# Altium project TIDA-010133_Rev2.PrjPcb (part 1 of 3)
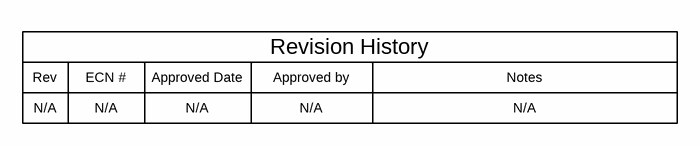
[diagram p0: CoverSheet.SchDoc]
CCA REV: A; CopyrightYear: 2023; ESD REV: A; EVM_orderable: N/A; PCB_Layout: TESSOLVE; PCB_Rev: B; PRJ_Customer: Public Release; PRJ_Engineer: Rob Stoneham; PRJ_Number: TIDA-010133; PRJ_Title: TIDA-010133; SCH_Rev: B; TechSupport: http://www.ti.com/support; TID: N/A
8 sheets, 588 parts. Net scope: flat (ports and power ports of the same name join across sheets).
Board file: TIDA010133_PCB.PcbDoc
Sheets:
  CoverSheet.SchDoc
  1_BUF802_CH1_AFE.SchDoc
  2_BUF802_CH2_AFE.SchDoc
  3_BUF802_OFFSET_TRIGGER.SchDoc
  4_BUF802_USBIF.SchDoc
  5_BUF802_PWR_PG1.SchDoc
  6_BUF802_PWR_PG2.SchDoc
  EVM_Hardware.SchDoc

## Sheet CoverSheet.SchDoc: CoverSheet
size 431 x 279 mm; Date: Not shown in title block; ApprovedBy: Not shown in title block; CheckedBy: Not shown in title block; Author: Not shown in title block; CompanyName: Not shown in title block; DrawnBy: Rob Stoneham; Engineer: Not shown in title block; Organization: Not shown in title block; Address1: Not shown in title block; Address2: Not shown in title block; Address3: Not shown in title block; Address4: Not shown in title block; DocumentNumber: 1; Revision: Use project parameter SCH_Rev; SheetNumber: 1; SheetTotal: 8; PageSetup: Record=PageOptions¦CenterHorizontal=True¦CenterVertical=True¦PrintScale=1.00¦XCorrection=1.00¦YCorrection=1.00¦PrintKind=0¦BorderSize=5000000¦LeftOffset=0¦BottomOffset=0¦Orientation=2¦PaperLength=1000¦PaperWidth=1000¦Scale=100¦PaperSource=15¦PrintQuality=600¦MediaType=1¦DitherType=10¦PaperKind=Letter¦PrintScaleMode=1

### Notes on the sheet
- Rev
- N/A
- ECN #
- Approved Date
- Approved by
- Revision History
- Notes

## Sheet 1_BUF802_CH1_AFE.SchDoc: 1_BUF802_CH1_AFE
size 431 x 279 mm; Date: Not shown in title block; ApprovedBy: Not shown in title block; CheckedBy: Not shown in title block; Author: Not shown in title block; CompanyName: Not shown in title block; DrawnBy: Rob Stoneham; Engineer: Not shown in title block; Organization: Not shown in title block; Address1: Not shown in title block; Address2: Not shown in title block; Address3: Not shown in title block; Address4: Not shown in title block; DocumentNumber: 2; Revision: Use project parameter SCH_Rev; SheetNumber: 2; SheetTotal: 8; PageSetup: Record=PageOptions¦CenterHorizontal=True¦CenterVertical=True¦PrintScale=1.00¦XCorrection=1.00¦YCorrection=1.00¦PrintKind=0¦BorderSize=5000000¦LeftOffset=0¦BottomOffset=0¦Orientation=2¦PaperLength=1000¦PaperWidth=1000¦Scale=100¦PaperSource=15¦PrintQuality=600¦MediaType=1¦DitherType=10¦PaperKind=Letter¦PrintScaleMode=1
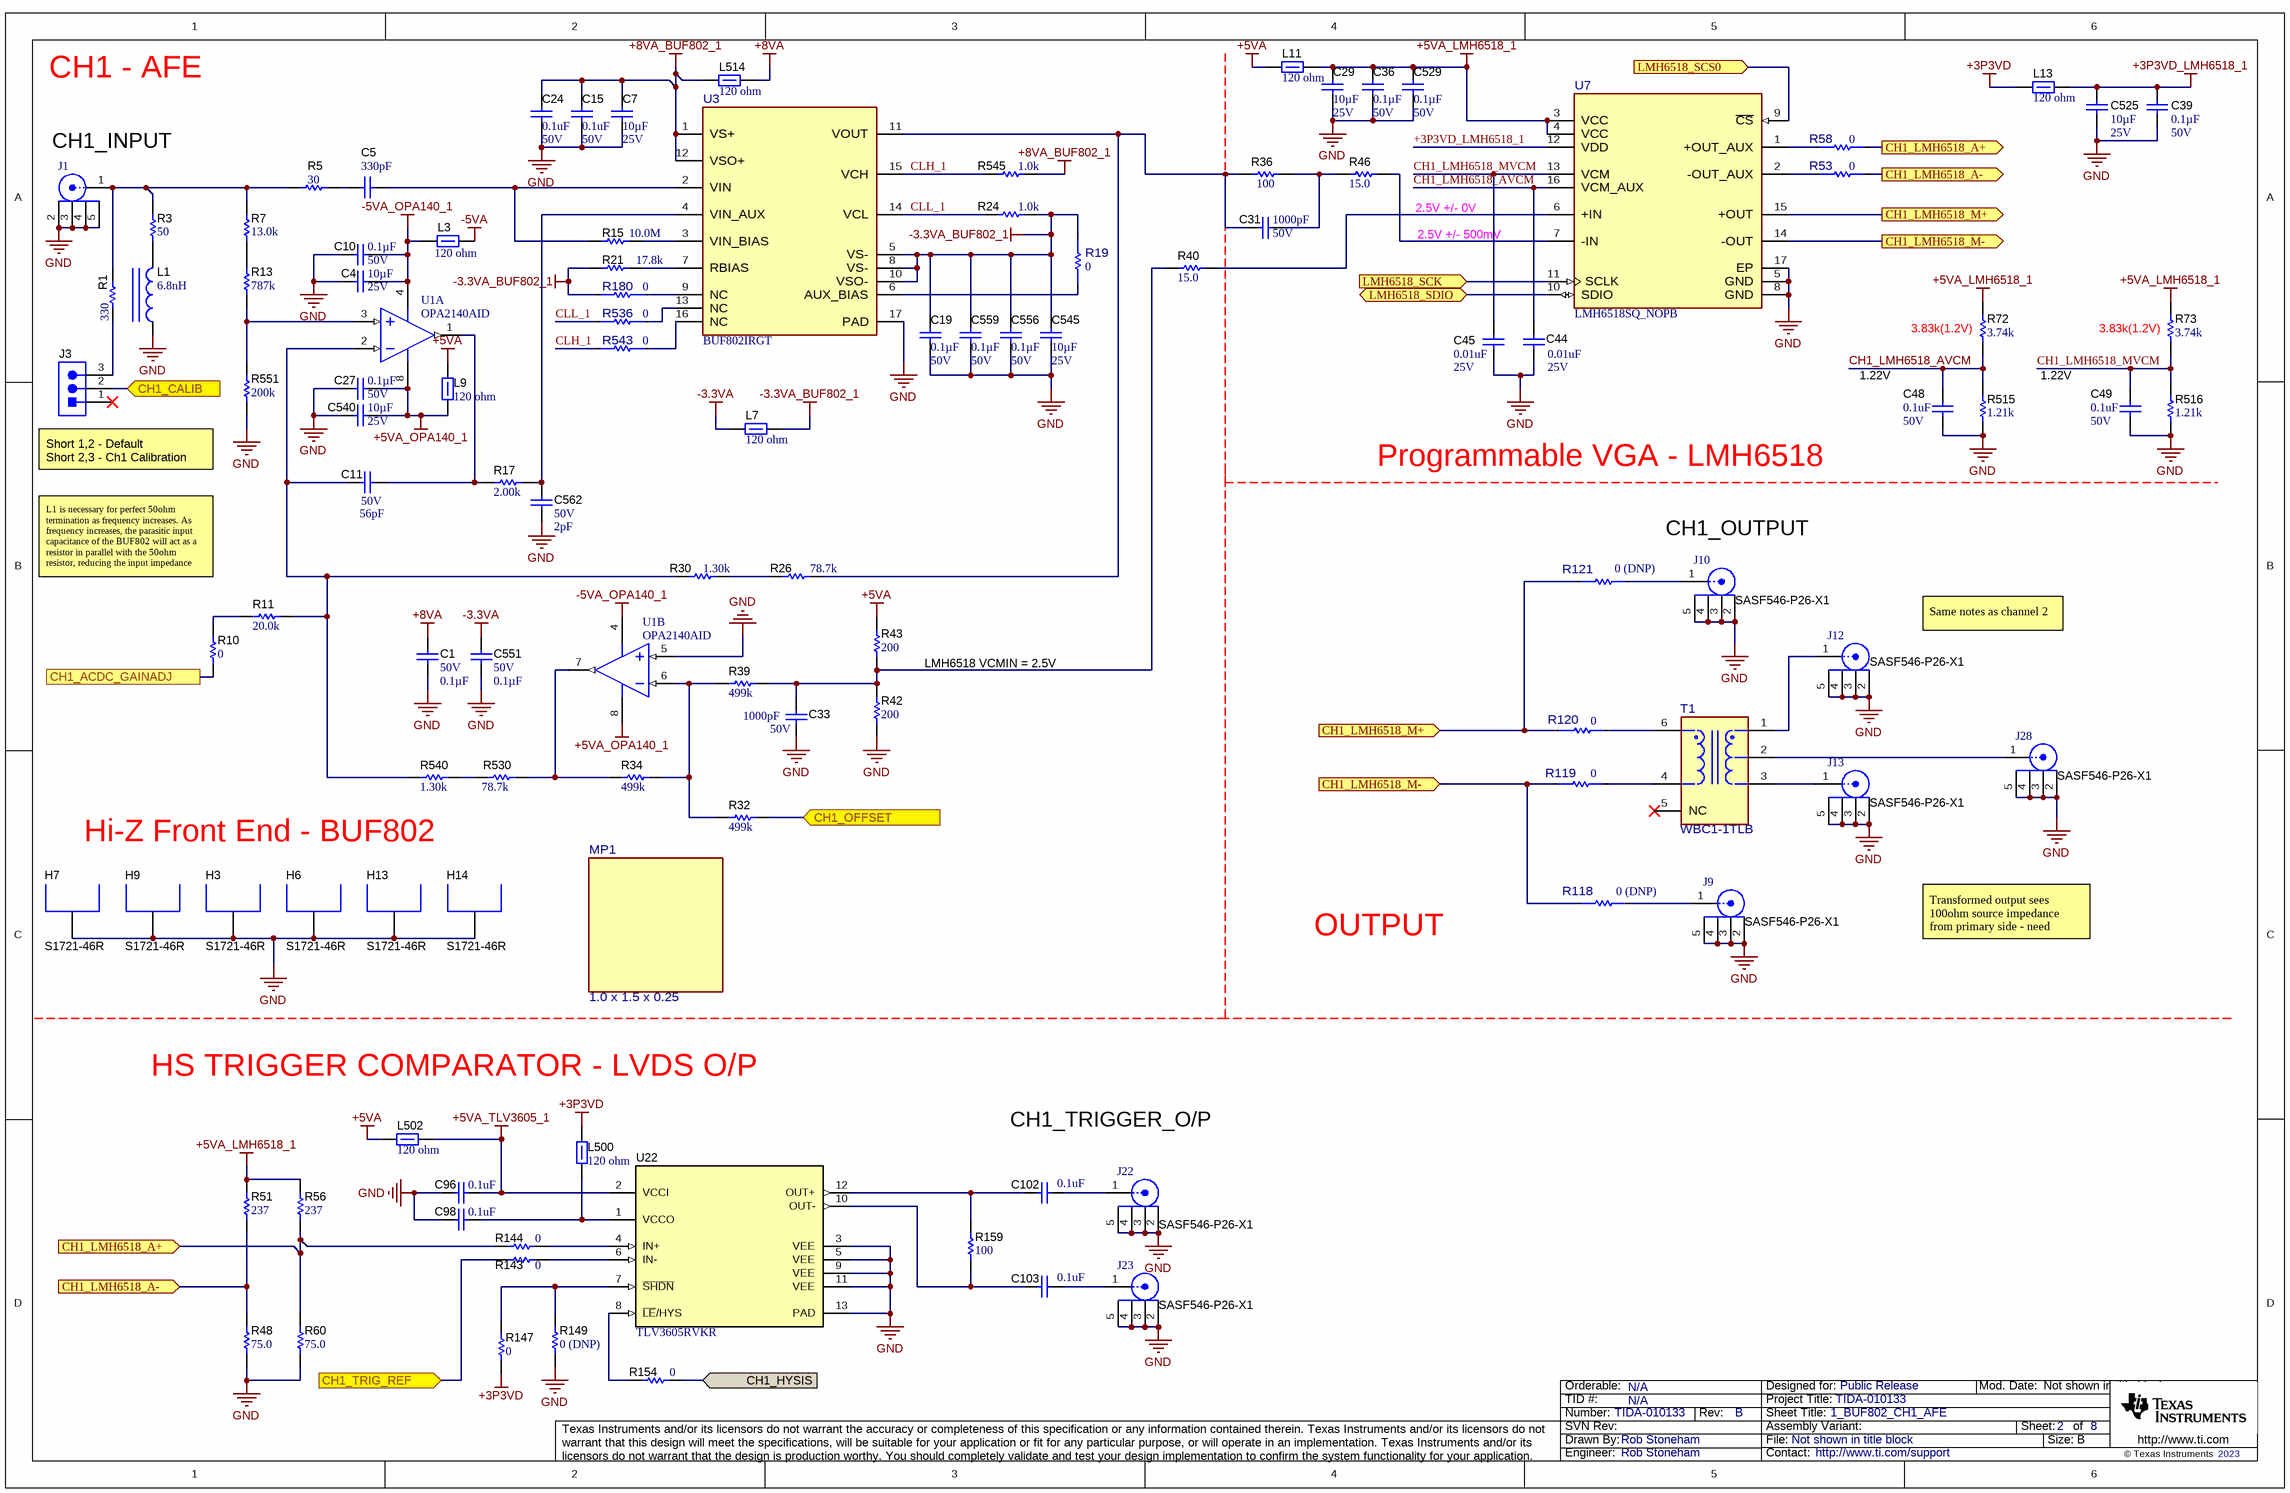
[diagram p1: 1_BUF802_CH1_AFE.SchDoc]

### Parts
C1  VDC_V: 50V  ValueDisplayed: 0.1µF  [0402]  (hidden comment: 0402BB104KW500)
C4  VDC_V: 25V  ValueDisplayed: 10µF  [0805_HV]  (hidden comment: CC0805KKX5R8BB106)
C5  ValueDisplayed: 330pF  [1206]  (hidden comment: GRM31A5C2J331JW01D)
C7  VDC_V: 25V  ValueDisplayed: 10µF  [0805_HV]  (hidden comment: CC0805KKX5R8BB106)
C10  VDC_V: 50V  ValueDisplayed: 0.1µF  [0402]  (hidden comment: 0402BB104KW500)
C11  VDC_V: 50V  ValueDisplayed: 56pF  [0402]  (hidden comment: GRM1555C1H560JA01D)
C15  ValueDisplayed: 0.1uF  Value2: 50V  [0603]  (hidden comment: CGA3E2X7R1H104K080AA)
C19  VDC_V: 50V  ValueDisplayed: 0.1µF  [0402]  (hidden comment: 0402BB104KW500)
C24  ValueDisplayed: 0.1uF  Value2: 50V  [0603]  (hidden comment: CGA3E2X7R1H104K080AA)
C27  VDC_V: 50V  ValueDisplayed: 0.1µF  [0402]  (hidden comment: 0402BB104KW500)
C29  VDC_V: 25V  ValueDisplayed: 10µF  [0805_HV]  (hidden comment: CC0805KKX5R8BB106)
C31  VDC_V: 50V  ValueDisplayed: 1000pF  [0402]  (hidden comment: 885012205061)
C33  VDC_V: 50V  ValueDisplayed: 1000pF  [0402]  (hidden comment: 885012205061)
C36  VDC_V: 50V  ValueDisplayed: 0.1µF  [0402]  (hidden comment: 0402BB104KW500)
C39  VDC_V: 50V  ValueDisplayed: 0.1µF  [0402]  (hidden comment: 0402BB104KW500)
C44  ValueDisplayed: 0.01uF  VDC_V: 25V  [0306]  (hidden comment: LLL185R71E103MA01L)
C45  ValueDisplayed: 0.01uF  VDC_V: 25V  [0306]  (hidden comment: LLL185R71E103MA01L)
C48  ValueDisplayed: 0.1uF  VDC_V: 50V  [0603]  (hidden comment: CGA3E2X7R1H104K080AA)
C49  ValueDisplayed: 0.1uF  VDC_V: 50V  [0603]  (hidden comment: CGA3E2X7R1H104K080AA)
C96  ValueDisplayed: 0.1uF  [0603]  (hidden comment: CGA3E2X7R1H104K080AA)
C98  ValueDisplayed: 0.1uF  [0603]  (hidden comment: CGA3E2X7R1H104K080AA)
C102  ValueDisplayed: 0.1uF  [0402]  (hidden comment: C1005X7R1E104M050BB)
C103  ValueDisplayed: 0.1uF  [0402]  (hidden comment: C1005X7R1E104M050BB)
C525  VDC_V: 25V  ValueDisplayed: 10µF  [0805_HV]  (hidden comment: CC0805KKX5R8BB106)
C529  VDC_V: 50V  ValueDisplayed: 0.1µF  [0402]  (hidden comment: 0402BB104KW500)
C540  VDC_V: 25V  ValueDisplayed: 10µF  [0805_HV]  (hidden comment: CC0805KKX5R8BB106)
C545  VDC_V: 25V  ValueDisplayed: 10µF  [0805_HV]  (hidden comment: CC0805KKX5R8BB106)
C551  VDC_V: 50V  ValueDisplayed: 0.1µF  [0402]  (hidden comment: 0402BB104KW500)
C556  VDC_V: 50V  ValueDisplayed: 0.1µF  [0402]  (hidden comment: 0402BB104KW500)
C559  VDC_V: 50V  ValueDisplayed: 0.1µF  [0402]  (hidden comment: 0402BB104KW500)
C562  VDC_V: 50V  ValueDisplayed: 2pF  [0603]  (hidden comment: C0603C209C5GACTU)
H3  S1721-46R  [Harwin_S1721-46R]
H6  S1721-46R  [Harwin_S1721-46R]
H7  S1721-46R  [Harwin_S1721-46R]
H9  S1721-46R  [Harwin_S1721-46R]
H13  S1721-46R  [Harwin_S1721-46R]
H14  S1721-46R  [Harwin_S1721-46R]
J1  142-0701-851  [Emerson_142-0701-851]  (value not drawn)
J3  22284030  [Molex_0022284030]  (value not drawn)
J9  SASF546-P26-X1  [CONN_LTI_SASF546-P26-X1]
J10  SASF546-P26-X1  [CONN_LTI_SASF546-P26-X1]
J12  SASF546-P26-X1  [CONN_LTI_SASF546-P26-X1]
J13  SASF546-P26-X1  [CONN_LTI_SASF546-P26-X1]
J22  SASF546-P26-X1  [CONN_LTI_SASF546-P26-X1]
J23  SASF546-P26-X1  [CONN_LTI_SASF546-P26-X1]
J28  SASF546-P26-X1  [CONN_LTI_SASF546-P26-X1]
L1  ValueDisplayed: 6.8nH  [LQG15WZ_02]  (hidden comment: LQG15WZ6N8J02D)
L3  ValueDisplayed: 120 ohm  [0603]  (hidden comment: BLM18SG121TN1D)
L7  ValueDisplayed: 120 ohm  [0603]  (hidden comment: BLM18SG121TN1D)
L9  ValueDisplayed: 120 ohm  [0603]  (hidden comment: BLM18SG121TN1D)
L11  ValueDisplayed: 120 ohm  [0603]  (hidden comment: BLM18SG121TN1D)
L13  ValueDisplayed: 120 ohm  [0603]  (hidden comment: BLM18SG121TN1D)
L500  ValueDisplayed: 120 ohm  [0603]  (hidden comment: BLM18SG121TN1D)
L502  ValueDisplayed: 120 ohm  [0603]  (hidden comment: BLM18SG121TN1D)
L514  ValueDisplayed: 120 ohm  [0603]  (hidden comment: BLM18SG121TN1D)
MP1  1.0 x 1.5 x 0.25  [FP-1.0 x 1.5 x 0.25_RF_SHIELD-MFG]
R1  ValueDisplayed: 330  [0603]  (hidden comment: RC0603FR-07330RL)
R3  ValueDisplayed: 50  [0603]  (hidden comment: FC0603E50R0BTBST1)
R5  ValueDisplayed: 30  [0402]  (hidden comment: CRCW040230R0JNED)
R7  ValueDisplayed: 13.0k  [0402L]  (hidden comment: CRCW040213K0FKED)
R10  ValueDisplayed: 0  [0603]  (hidden comment: CRCW06030000Z0EA)
R11  ValueDisplayed: 20.0k  [0402]  (hidden comment: CRCW040220K0FKED)
R13  ValueDisplayed: 787k  [0402L]  (hidden comment: CRCW0402787KFKED)
R15  ValueDisplayed: 10.0M  [0402]  (hidden comment: CRCW040210M0FKED)
R17  ValueDisplayed: 2.00k  [0402]  (hidden comment: ERJ-2RKF2001X)
R19  value 0  [FP-ERJ-2GE0R00X_0402-MFG]  (hidden comment: ERJ-2GE0R00X)
R21  ValueDisplayed: 17.8k  [0402]  (hidden comment: CRCW040217K8FKED)
R24  ValueDisplayed: 1.0k  [0603]  (hidden comment: RC0603JR-071KL)
R26  ValueDisplayed: 78.7k  [0402]  (hidden comment: CRCW040278K7FKED)
R30  ValueDisplayed: 1.30k  [0402]  (hidden comment: CRCW04021K30FKED)
R32  ValueDisplayed: 499k  [0402]  (hidden comment: CRCW0402499KFKED)
R34  ValueDisplayed: 499k  [0402]  (hidden comment: CRCW0402499KFKED)
R36  ValueDisplayed: 100  [0402]  (hidden comment: CRCW0402100RFKED)
R39  ValueDisplayed: 499k  [0402]  (hidden comment: CRCW0402499KFKED)
R40  ValueDisplayed: 15.0  [0402]  (hidden comment: CRCW040215R0FKED)
R42  ValueDisplayed: 200  [0402]  (hidden comment: CRCW0402200RFKED)
R43  ValueDisplayed: 200  [0402]  (hidden comment: CRCW0402200RFKED)
R46  ValueDisplayed: 15.0  [0402]  (hidden comment: CRCW040215R0FKED)
R48  ValueDisplayed: 75.0  [0603]  (hidden comment: CRCW060375R0FKEA)
R51  ValueDisplayed: 237  [0603]  (hidden comment: CRCW0603237RFKEA)
R53  value 0  [FP-CRCW04020000Z0EDHP_0402-MFG]  (hidden comment: CRCW04020000Z0EDHP)
R56  ValueDisplayed: 237  [0603]  (hidden comment: CRCW0603237RFKEA)
R58  value 0  [FP-CRCW04020000Z0EDHP_0402-MFG]  (hidden comment: CRCW04020000Z0EDHP)
R60  ValueDisplayed: 75.0  [0603]  (hidden comment: CRCW060375R0FKEA)
R72  ValueDisplayed: 3.74k  [0603]  (hidden comment: RC0603FR-073K74L)
R73  ValueDisplayed: 3.74k  [0603]  (hidden comment: RC0603FR-073K74L)
R118  value 0 (DNP)  [FP-CRCW04020000Z0EDHP_0402-MFG]  (hidden comment: CRCW04020000Z0EDHP)
R119  value 0  [FP-CRCW04020000Z0EDHP_0402-MFG]  (hidden comment: CRCW04020000Z0EDHP)
R120  value 0  [FP-CRCW04020000Z0EDHP_0402-MFG]  (hidden comment: CRCW04020000Z0EDHP)
R121  value 0 (DNP)  [FP-CRCW04020000Z0EDHP_0402-MFG]  (hidden comment: CRCW04020000Z0EDHP)
R143  ValueDisplayed: 0  [0402]  (hidden comment: CRCW04020000Z0ED)
R144  ValueDisplayed: 0  [0402]  (hidden comment: CRCW04020000Z0ED)
R147  ValueDisplayed: 0  [0603]  (hidden comment: CRCW06030000Z0EA)
R149  ValueDisplayed: 0 (DNP)  [0402]  (hidden comment: CRCW04020000Z0ED)
R154  ValueDisplayed: 0  [0402]  (hidden comment: CRCW04020000Z0ED)
R159  ValueDisplayed: 100  [0402]  (hidden comment: CRCW0402100RFKED)
R180  value 0  [FP-ERJ-2GE0R00X_0402-MFG]  (hidden comment: ERJ-2GE0R00X)
R515  ValueDisplayed: 1.21k  [0603]  (hidden comment: RC0603FR-071K21L)
R516  ValueDisplayed: 1.21k  [0603]  (hidden comment: RC0603FR-071K21L)
R530  ValueDisplayed: 78.7k  [0402]  (hidden comment: CRCW040278K7FKED)
R536  value 0  [FP-ERJ-2GE0R00X_0402-MFG]  (hidden comment: ERJ-2GE0R00X)
R540  ValueDisplayed: 1.30k  [0402]  (hidden comment: CRCW04021K30FKED)
R543  value 0  [FP-ERJ-2GE0R00X_0402-MFG]  (hidden comment: ERJ-2GE0R00X)
R545  ValueDisplayed: 1.0k  [0603]  (hidden comment: RC0603JR-071KL)
R551  ValueDisplayed: 200k  [0402L]  (hidden comment: CRCW0402200KFKED)
T1  WBC1-1TLB  [FP-WBC1-1TLB_SMT_XFRMR_3MM81_3MM81-MFG]
U1  OPA2140AID  [D0008A_N]  (parts A,B of 2)
U3  BUF802IRGT  [RGT0016C-MFG]
U7  LMH6518SQ_NOPB  [RGH0016A-MFG]
U22  TLV3605RVKR  [RVK0012A]

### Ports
CH1_ACDC_GAINADJ, CH1_CALIB (in), CH1_HYSIS (in), CH1_LMH6518_A+ (in), CH1_LMH6518_A+ (out), CH1_LMH6518_A- (in), CH1_LMH6518_A- (out), CH1_LMH6518_M+ (in), CH1_LMH6518_M+ (out), CH1_LMH6518_M- (in), CH1_LMH6518_M- (out), CH1_OFFSET (in), CH1_TRIG_REF (in), LMH6518_SCK (in), LMH6518_SCS0 (in), LMH6518_SDIO (bidir)

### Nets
+3P3VD: L13.1 L500.2 R147.1
+3P3VD_LMH6518_1: C39.1 C525.1 L13.2 U7.12(VDD)
+5VA: L9.2 L11.1 L502.1 R43.2
+5VA_LMH6518_1: C29.1 C36.1 C529.1 L11.2 R51.2 R56.2 R72.2 R73.2 U7.3(VCC) U7.4(VCC)
+5VA_OPA140_1: C27.2 C540.2 L9.1 U1.8(V+)
+5VA_TLV3605_1: C96.2 L502.2 U22.2(VCCI)
+8VA: C1.1 L514.2
+8VA_BUF802_1: C7.1 C15.1 C24.1 L514.1 R545.2 U3.1(VS+) U3.12(VSO+)
-3.3VA: C551.2 L7.1
-3.3VA_BUF802_1: C19.1 C545.1 C556.1 C559.1 L7.2 R19.2 R21.1 R24.2 R180.2 U3.5(VS-) U3.8(VS-) U3.10(VSO-)
-5VA: L3.2
-5VA_OPA140_1: C4.2 C10.2 L3.1 U1.4(V-)
GND: C1.2 C4.1 C7.2 C10.1 C15.2 C19.2 C24.2 C27.1 C29.2 C33.2 C36.2 C39.2 C44.2 C45.2 C48.2 C49.2 C96.1 C98.2 C525.2 C529.2 C540.1 C545.2 C551.1 C556.2 C559.2 C562.2 H3.1 H6.1 H7.1 H9.1 H13.1 H14.1 J1.2 J1.3 J1.4 J1.5 J9.2 J9.3 J9.4 J9.5 J10.2 J10.3 J10.4 J10.5 J12.2 J12.3 J12.4 J12.5 J13.2 J13.3 J13.4 J13.5 J22.2 J22.3 J22.4 J22.5 J23.2 J23.3 J23.4 J23.5 J28.2 J28.3 J28.4 J28.5 L1.1 R42.1 R48.1 R60.1 R149.1 R515.1 R516.1 R551.1 U1.5(IN_B+) U3.17(PAD) U7.5(GND) U7.8(GND) U7.17(EP) U22.3(VEE) U22.5(VEE) U22.9(VEE) U22.11(VEE) U22.13(PAD)
CH1_ACDC_GAINADJ: R10.2 ; port CH1_ACDC_GAINADJ
CH1_CALIB: J3.2 ; port CH1_CALIB
CH1_HYSIS: R154.2 ; port CH1_HYSIS
CH1_LMH6518_A+: R56.1 R58.2 R60.2 R144.1 ; port CH1_LMH6518_A+
CH1_LMH6518_A-: R48.2 R51.1 R53.2 ; port CH1_LMH6518_A-
CH1_LMH6518_AVCM: C44.1 C48.1 R72.1 R515.2 U7.16(VCM_AUX)
CH1_LMH6518_M+: R120.1 R121.1 U7.15(+OUT) ; port CH1_LMH6518_M+
CH1_LMH6518_M-: R118.1 R119.1 U7.14(-OUT) ; port CH1_LMH6518_M-
CH1_LMH6518_MVCM: C45.1 C49.1 R73.1 R516.2 U7.13(VCM)
CH1_OFFSET: R32.2 ; port CH1_OFFSET
CH1_TRIG_REF: R143.1 ; port CH1_TRIG_REF
CLH_1: R543.2 R545.1 U3.15(VCH)
CLL_1: R24.1 R536.2 U3.14(VCL)
LMH6518_SCK: U7.11(SCLK) ; port LMH6518_SCK
LMH6518_SCS0: U7.9(~{CS}) ; port LMH6518_SCS0
LMH6518_SDIO: U7.10(SDIO) ; port LMH6518_SDIO
NetC5_1: C5.1 R15.1 U3.2(VIN)
NetC5_2: C5.2 R5.2
NetC11_1: C11.1 R17.1 U1.1(OUT_A)
NetC11_2: C11.2 R11.2 R30.1 R540.1 U1.2(IN_A-)
NetC31_1: C31.1 R26.2 R36.1 U3.11(VOUT)
NetC31_2: C31.2 R36.2 R46.1
NetC33_1: C33.1 R39.2 R40.1 R42.2 R43.1
NetC98_1: C98.1 L500.1 U22.1(VCCO)
NetC102_1: C102.1 R159.2 U22.12(OUT+)
NetC102_2: C102.2 J22.1
NetC103_1: C103.1 R159.1 U22.10(OUT-)
NetC103_2: C103.2 J23.1
NetC562_1: C562.1 R17.2 U3.4(VIN_AUX)
NetJ1_1: J1.1 R1.2 R3.2 R5.1 R7.2
NetJ3_3: J3.3 R1.1
NetJ9_1: J9.1 R118.2
NetJ10_1: J10.1 R121.2
NetJ12_1: J12.1 T1.1
NetJ13_1: J13.1 T1.3
NetJ28_1: J28.1 T1.2
NetL1_2: L1.2 R3.1
NetR7_1: R7.1 R13.2
NetR10_1: R10.1 R11.1
NetR13_1: R13.1 R551.2 U1.3(IN_A+)
NetR15_2: R15.2 U3.3(VIN_BIAS)
NetR19_1: R19.1 U3.6(AUX_BIAS)
NetR21_2: R21.2 U3.7(RBIAS)
NetR26_1: R26.1 R30.2
NetR32_1: R32.1 R34.2 R39.1 U1.6(IN_B-)
NetR34_1: R34.1 R530.2 U1.7(OUT_B)
NetR40_2: R40.2 U7.6(+IN)
NetR46_2: R46.2 U7.7(-IN)
NetR53_1: R53.1 U7.2(-OUT_AUX)
NetR58_1: R58.1 U7.1(+OUT_AUX)
NetR119_2: R119.2 T1.4
NetR120_2: R120.2 T1.6
NetR143_2: R143.2 U22.6(IN-)
NetR144_2: R144.2 U22.4(IN+)
NetR147_2: R147.2 R149.2 U22.7(~{SHDN})
NetR154_1: R154.1 U22.8(~{LE}/HYS)
NetR180_1: R180.1 U3.9(NC)
NetR530_1: R530.1 R540.2
NetR536_1: R536.1 U3.13(NC)
NetR543_1: R543.1 U3.16(NC)

Not connected (* = marked no-connect by the designer): J3 1*; T1 5(NC)*

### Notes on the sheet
- CH1 - AFE
- (near J1) CH1_INPUT
- (near R46) 2.5V +/- 0V
- 2.5V +/- 500mV
- 1.22V
- (near R72) 3.83k(1.2V)
- (near R73) 3.83k(1.2V)
- Short 1,2 - Default
  Short 2,3 - Ch1 Calibration
- Programmable VGA - LMH6518
- L1 is necessary for perfect 50ohm termination as frequency increases. As frequency increases, the parasitic input capacitance of the BUF802 will act as a resistor in parallel with the 50ohm resistor, reducing the input impedance
- (near J10) CH1_OUTPUT
- Same notes as channel 2
- LMH6518 VCMIN = 2.5V
- (near R540) Hi-Z Front End - BUF802
- OUTPUT
- Transformed output sees 100ohm source impedance from primary side - need different transformer
- HS TRIGGER COMPARATOR - LVDS O/P
- CH1_TRIGGER_O/P

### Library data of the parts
C1 C10 C19 C27 C36 C39 C529 C551 C556 C559 = CMP-0860983-1: CAP, CERM, 0.1 µF, 50 V,+/- 10%, X7R, 0402; Manufacturer: Passive Plus; TaMax_C: 125°C; U/M: EA; SizeY_mm: 0.5; TaMin_C: -55°C; SizeAreaWB_mm2: 3; Value: 0.1uF; AEC Qualified: N; SizeX_mm: 1; AEC Category: Q200; SizeZ_mm: 0.6; Cap_F: 100nF
C4 C7 C29 C525 C540 C545 = CMP-0084177-1: CAP, CERM, 10 µF, 25 V,+/- 10%, X5R, 0805; Manufacturer: Yageo; SizeAreaWB_mm2: 6.75; SizeArea_mm2: 2.5; AEC Qualified: N; AEC Category: Q200; Value: 10uF; TaMax_C: 85°C; SizeZ_mm: 1.45; TaMin_C: -55°C; SizeY_mm: 1.25; U/M: EA; SizeX_mm: 2; Cap_Case: 0805
C5 = CMP-0008887-2: CAP, CERM, 330 pF, 630 V, +/- 5%, C0G/NP0, 1206; Manufacturer: MuRata; TaMin_C: -55°C; Polarized: N; SizeAreaWB_mm2: 10.92; Value1: Unknown; U/M: EA; Value: 330pF; TaMax_C: 125°C; SizeZ_mm: 1.35; SizeX_mm: 3.2; SizeY_mm: 1.6; Value2: 630V; SizeArea_mm2: 5.12; AEC Category: Q200
C11 = CMP-0006478-2: CAP, CERM, 56 pF, 50 V, +/- 5%, C0G/NP0, 0402; Manufacturer: MuRata; TaMin_C: -55°C; Polarized: N; SizeAreaWB_mm2: 3; Value1: Unknown; U/M: EA; Value: 56pF; TaMax_C: 125°C; SizeZ_mm: 0.6; SizeX_mm: 1; SizeY_mm: 0.5; AEC Category: Q200
C15 C24 C48 C49 = CMP-0007078-4: CAP, CERM, 0.1 uF, 50 V, +/- 10%, X7R, AEC-Q200 Grade 1, 0603; Manufacturer: TDK; Polarized: N; Value: 0.1uF; U/M: EA; Cap_F: 100nF; ESR_ohm: 29.6m; Value1: 0.0296 ohm; IRMS_A: 971.99mA; TaMin_C: -55°C; TaMax_C: 125°C; SizeArea_mm2: 1.28; SizeAreaWB_mm2: 4.68; SizeX_mm: 1.6; SizeY_mm: 0.8; SizeZ_mm: 1; AEC Category: Q200; AEC Qualified: Y
C31 C33 = CMP-0006231-2: CAP, CERM, 1000 pF, 50 V, +/- 10%, X7R, 0402; Manufacturer: Wurth Elektronik; TaMin_C: -55°C; Polarized: N; SizeAreaWB_mm2: 3; Value1: Unknown; U/M: EA; Value: 1000pF; TaMax_C: 125°C; SizeZ_mm: 0.6; SizeX_mm: 1; SizeY_mm: 0.5; Cap_F: 1nF; AEC Category: Q200
C44 C45 = CMP-0009490-2: CAP, CERM, 0.01 uF, 25 V, +/- 20%, X7R, 0306; Manufacturer: MuRata; Polarized: N; Value: 0.01uF; U/M: EA; Cap_F: 10nF; Value1: Unknown; TaMin_C: -55°C; TaMax_C: 125°C; SizeArea_mm2: 1.28; SizeAreaWB_mm2: 4.68; SizeX_mm: 0.8; SizeY_mm: 1.6; SizeZ_mm: 0.6; AEC Category: Q200
C96 C98 = CMP-0007078-4: CAP, CERM, 0.1 uF, 50 V, +/- 10%, X7R, AEC-Q200 Grade 1, 0603; Manufacturer: TDK; Polarized: N; Value: 0.1uF; U/M: EA; Cap_F: 100nF; ESR_ohm: 29.6m; Value1: 0.0296 ohm; VDC_V: 50V; IRMS_A: 971.99mA; TaMin_C: -55°C; TaMax_C: 125°C; SizeArea_mm2: 1.28; SizeAreaWB_mm2: 4.68; SizeX_mm: 1.6; SizeY_mm: 0.8; SizeZ_mm: 1; AEC Category: Q200; AEC Qualified: Y
C102 C103 = CMP-0006295-2: CAP, CERM, 0.1 uF, 25 V, +/- 20%, X7R, 0402; Manufacturer: TDK; Polarized: N; TaMax_C: 125°C; TaMin_C: -55°C; VDC_V: 25V; Cap_F: 100nF; Value: 0.1uF; Value1: Unknown; U/M: EA; SizeArea_mm2: 0.5; SizeAreaWB_mm2: 3; SizeX_mm: 1; SizeZ_mm: 0.6; AEC Category: Q200
C562 = CMP-0006891-4: CAP, CERM, 2 pF, 50 V, +/- 12.5%, C0G/NP0, 0603; Manufacturer: Kemet; TaMin_C: -55°C; Polarized: N; SizeAreaWB_mm2: 4.68; Value1: Unknown; U/M: EA; Value: 2pF; TaMax_C: 125°C; SizeX_mm: 1.6; SizeY_mm: 0.8; SizeArea_mm2: 1.28; SizeZ_mm: 1; AEC Category: Q200
H3 H6 H7 H9 H13 H14 = CMP-0086134-1: RFI SHIELD CLIP TIN SMD; Manufacturer: Harwin
J1 = CMP-0055822-3: Connector, End launch SMA, 50 ohm, SMT; Manufacturer: Cinch Connectivity; Green_Lifecycle: Not Set; Green_REACh: Incomplete
J3 = CMP-0078237-1: Header, 2.54mm, 3x1, Tin, TH; Manufacturer: Molex; Pitch_mm: 2.54; Gender: Male; Cert_CSA: Y; Current_A: 4A; Voltage_V: 500V; Shrouded: N; Row_Count: 1
J9 J10 J12 J13 J22 J23 J28 = CMP-0055826-1: Connector, SMA,Vertical, Thru hole w/SMT center pin; Manufacturer: Lighthorse Technologies; CT: TRUE; Green_REACh: Incomplete; CNHeader: FALSE; Green_Lifecycle: Not Set
L1 = CMP-0080319-3: Inductor, Multilayer, Air Core, 6.8 nH, 0.7 A, 0.14 ohm, AEC-Q200 Grade 1, SMD; Manufacturer: MuRata; Irms: 0.7A @ 25C rise; SizeAreaWB_mm2: 3.2; DCR_ohm: 0.14; Value: 6.8nH; Imax_A: 700mA; SizeZ_mm: 0.6; SizeX_mm: 1; Value2: 0.7A; AEC Qualified: Y; AEC Category: Q200
L3 L7 L9 L11 L13 L500 L502 L514 = CMP-0003352-2: Ferrite Bead, 120 ohm @ 100 MHz, 3 A, 0603; Manufacturer: MuRata; Value: 120 ohm; Imax_A: 3A; DCR_ohm: 25m; Value1: 0.025 ohm; SizeAreaWB_mm2: 4.68; SizeArea_mm2: 1.28; SizeX_mm: 1.6; SizeY_mm: 0.8; SizeZ_mm: 1; ZTyp@100MHz_Ohm: 120
MP1 = CMP-0096146-1: Standard RF Shield 1.0 x 1.5 x 0.25; Manufacturer: Fotofab; AEC Qualified: No; SizeZ_mm: 0.25inch
R1 = CMP-0023033-5: RES, 330, 1%, 0.1 W, 0603; Manufacturer: Yageo; Power_W: 100mW; TempCo: 100 ppm/C; Value_Code: 330R; Value: 330; SizeX_mm: 1.6; SizeY_mm: 0.8; SizeZ_mm: 1; Value2: 0.1W; SizeArea_mm2: 1.28; AEC Qualified: N; VDC_V: 75V; AEC Category: Q200; SizeAreaWB_mm2: 4.68
R3 = CMP-0023387-3: RES, 50, 0.1%, 0.125 W, 0603; Manufacturer: Vishay Thin Film; Power_W: 125mW; TempCo: 25 ppm/C; Value_Code: 50R0; U/M: EA; Value: 50; SizeX_mm: 1.6; SizeY_mm: 0.8; SizeZ_mm: 1; Value2: 0.125W; SizeArea_mm2: 1.28; AEC Qualified: N; VDC_V: 50V; AEC Category: Q200
R5 = CMP-0026904-3: RES, 30, 5%, 0.063 W, AEC-Q200 Grade 0, 0402; Manufacturer: Vishay-Dale; Power_W: 63mW; TempCo: 200 ppm/C; Value_Code: 30R0; Value: 30; EIA_Code: E24; SizeX_mm: 1; SizeY_mm: 0.5; SizeZ_mm: 0.6; Value2: 0.063W; AEC Qualified: Y; VDC_V: 50V; AEC Category: Q200; AEC Grade: 0
R7 = CMP-0026003-3: RES, 13.0 k, 1%, 0.063 W, AEC-Q200 Grade 0, 0402; Manufacturer: Vishay-Dale; Power_W: 63mW; TempCo: 100 ppm/C; Value_Code: 13k0; Value: 13.0k; EIA_Code: E96; Res_ohm: 13k; SizeX_mm: 1; SizeY_mm: 0.5; SizeZ_mm: 0.6; Value2: 0.063W; AEC Qualified: Y; VDC_V: 50V; AEC Category: Q200; AEC Grade: 0
R10 = CMP-0025697-4: RES, 0, 5%, 0.1 W, AEC-Q200 Grade 0, 0603; Manufacturer: Vishay-Dale; Power_W: 100mW; TempCo: 200 ppm/C; Value_Code: 0000; Value: 0; EIA_Code: E24; SizeX_mm: 1.6; SizeY_mm: 0.8; SizeZ_mm: 1; Value2: 0.1W; SizeArea_mm2: 1.28; AEC Qualified: Y; VDC_V: 75V; AEC Category: Q200
R11 = CMP-0026162-2: RES, 20.0 k, 1%, 0.063 W, AEC-Q200 Grade 0, 0402; Manufacturer: Vishay-Dale; Power_W: 63mW; TempCo: 100 ppm/C; Value_Code: 20k0; Value: 20.0k; EIA_Code: E96; Res_ohm: 20k; SizeX_mm: 1; SizeY_mm: 0.5; SizeZ_mm: 0.6; Value2: 0.063W; AEC Qualified: Y; VDC_V: 50V; AEC Category: Q200; AEC Grade: 0
R13 = CMP-0026549-2: RES, 787 k, 1%, 0.063 W, AEC-Q200 Grade 0, 0402; Manufacturer: Vishay-Dale; Power_W: 63mW; TempCo: 100 ppm/C; Value: 787k; EIA_Code: E96; SizeX_mm: 1; SizeY_mm: 0.5; SizeZ_mm: 0.6; Value2: 0.063W; AEC Qualified: Y; VDC_V: 50V; AEC Category: Q200; AEC Grade: 0
R15 = CMP-0025962-3: RES, 10.0 M, 1%, 0.063 W, AEC-Q200 Grade 0, 0402; Manufacturer: Vishay-Dale; Power_W: 63mW; TempCo: 100 ppm/C; Value_Code: 10M0; Value: 10.0Meg; EIA_Code: E96; Res_ohm: 10M; SizeX_mm: 1; SizeY_mm: 0.5; SizeZ_mm: 0.6; Value2: 0.063W; AEC Qualified: Y; VDC_V: 50V; AEC Category: Q200; AEC Grade: 0
R17 = CMP-0026676-1: RES, 2.00 k, 1%, 0.1 W, AEC-Q200 Grade 0, 0402; Manufacturer: Panasonic; Power_W: 100mW; TempCo: 100 ppm/C; Value_Code: 2k00; U/M: EA; Value: 2.00k; EIA_Code: E96; Res_ohm: 2k; SizeX_mm: 1; SizeY_mm: 0.5; SizeZ_mm: 0.6; Value2: 0.1W; AEC Qualified: Y; VDC_V: 50V; AEC Grade: 0; AEC Category: Q200
R19 R180 R536 R543 = CMP-0002710-1: 0 Ohms Jumper Chip Resistor 0402 (1005 Metric) Automotive AEC-Q200 Thick Film; Manufacturer: Panasonic; SizeZ_mm: 0.4mm; AEC Qualified: Yes; AEC Grade: Grade 0; Power: 100mW
R21 = CMP-0026051-3: RES, 17.8 k, 1%, 0.063 W, AEC-Q200 Grade 0, 0402; Manufacturer: Vishay-Dale; Power_W: 63mW; TempCo: 100 ppm/C; Value_Code: 17k8; Value: 17.8k; EIA_Code: E96; SizeX_mm: 1; SizeY_mm: 0.5; SizeZ_mm: 0.6; Value2: 0.063W; AEC Qualified: Y; VDC_V: 50V; AEC Category: Q200; AEC Grade: 0
R24 R545 = CMP-0025899-5: RES, 1.0 k, 5%, 0.1 W, 0603; Manufacturer: Yageo; Power_W: 100mW; TempCo: 100 ppm/C; Value_Code: 1k00; Value: 1.0k; EIA_Code: E24; Res_ohm: 1k; SizeX_mm: 1.6; SizeY_mm: 0.8; SizeZ_mm: 1; Value2: 0.1W; SizeArea_mm2: 1.28; AEC Qualified: N; VDC_V: 75V; AEC Category: Q200; SizeAreaWB_mm2: 4.68
R26 R530 = CMP-0026551-2: RES, 78.7 k, 1%, 0.063 W, AEC-Q200 Grade 0, 0402; Manufacturer: Vishay-Dale; Power_W: 63mW; TempCo: 100 ppm/C; Value_Code: 78k7; Value: 78.7k; EIA_Code: E96; SizeX_mm: 1; SizeY_mm: 0.5; SizeZ_mm: 0.6; Value2: 0.063W; AEC Qualified: Y; VDC_V: 50V; AEC Category: Q200; AEC Grade: 0
R30 R540 = CMP-0026082-3: RES, 1.30 k, 1%, 0.063 W, AEC-Q200 Grade 0, 0402; Manufacturer: Vishay-Dale; Power_W: 63mW; TempCo: 100 ppm/C; Value_Code: 1k30; Value: 1.30k; EIA_Code: E96; Res_ohm: 1.3k; SizeX_mm: 1; SizeY_mm: 0.5; SizeZ_mm: 0.6; Value2: 0.063W; AEC Qualified: Y; VDC_V: 50V; AEC Category: Q200; AEC Grade: 0
R32 R34 R39 = CMP-0026401-2: RES, 499 k, 1%, 0.063 W, AEC-Q200 Grade 0, 0402; Manufacturer: Vishay-Dale; Power_W: 63mW; TempCo: 100 ppm/C; Value: 499k; EIA_Code: E96; SizeX_mm: 1; SizeY_mm: 0.5; SizeZ_mm: 0.6; Value2: 0.063W; AEC Qualified: Y; VDC_V: 50V; AEC Category: Q200; AEC Grade: 0
R36 = CMP-0025951-3: RES, 100, 1%, 0.063 W, AEC-Q200 Grade 0, 0402; Manufacturer: Vishay-Dale; Power_W: 63mW; TempCo: 100 ppm/C; Value_Code: 100R; Value: 100; EIA_Code: E96; SizeX_mm: 1; SizeY_mm: 0.5; SizeZ_mm: 0.6; Value2: 0.063W; AEC Qualified: Y; VDC_V: 50V; AEC Category: Q200; AEC Grade: 0
R40 R46 = CMP-0026030-3: RES, 15.0, 1%, 0.063 W, AEC-Q200 Grade 0, 0402; Manufacturer: Vishay-Dale; Power_W: 63mW; TempCo: 100 ppm/C; Value_Code: 15R0; Value: 15.0; EIA_Code: E96; Res_ohm: 15; SizeX_mm: 1; SizeY_mm: 0.5; SizeZ_mm: 0.6; Value2: 0.063W; AEC Qualified: Y; VDC_V: 50V; AEC Category: Q200; AEC Grade: 0
R42 R43 = CMP-0026159-2: RES, 200, 1%, 0.063 W, AEC-Q200 Grade 0, 0402; Manufacturer: Vishay-Dale; Power_W: 63mW; TempCo: 100 ppm/C; Value_Code: 200R; Value: 200; EIA_Code: E96; SizeX_mm: 1; SizeY_mm: 0.5; SizeZ_mm: 0.6; Value2: 0.063W; AEC Qualified: Y; VDC_V: 50V; AEC Category: Q200; AEC Grade: 0
R48 R60 = CMP-0022590-4: RES, 75.0, 1%, 0.1 W, AEC-Q200 Grade 0, 0603; Manufacturer: Vishay-Dale; Power_W: 100mW; TempCo: 100 ppm/C; Value_Code: 75R0; Value: 75.0; EIA_Code: E96; Res_ohm: 75; SizeX_mm: 1.6; SizeY_mm: 0.8; SizeZ_mm: 1; Value2: 0.1W; SizeArea_mm2: 1.28; AEC Qualified: Y; VDC_V: 75V; AEC Category: Q200; AEC Grade: 0
R51 R56 = CMP-0022227-5: RES, 237, 1%, 0.1 W, AEC-Q200 Grade 0, 0603; Manufacturer: Vishay-Dale; Power_W: 100mW; TempCo: 100 ppm/C; Value_Code: 237R; Value: 237; EIA_Code: E96; SizeX_mm: 1.6; SizeY_mm: 0.8; SizeZ_mm: 1; Value2: 0.1W; SizeArea_mm2: 1.28; AEC Qualified: Y; VDC_V: 75V; AEC Category: Q200; AEC Grade: 0
R53 R58 R119 R120 = CMP-0001606-2: RES Thick Film, 0Ω, 0.2W, 0402; Manufacturer: Vishay Dale; AEC Qualified: Yes; SizeZ_mm: 0.4mm; AEC Grade: Grade 0; Power_W: 200mW; VDC_V: 50V
R72 R73 = CMP-0023087-5: RES, 3.74 k, 1%, 0.1 W, 0603; Manufacturer: Yageo; Power_W: 100mW; TempCo: 100 ppm/C; Value_Code: 3k74; Value: 3.74k; EIA_Code: E96; SizeX_mm: 1.6; SizeY_mm: 0.8; SizeZ_mm: 1; Value2: 0.1W; SizeArea_mm2: 1.28; AEC Qualified: N; VDC_V: 75V; AEC Category: Q200; SizeAreaWB_mm2: 4.68
R118 R121 = CMP-0001606-2: RES Thick Film, 0Ω, 0.2W, 0402; Manufacturer: Vishay Dale; AEC Qualified: Yes; Res_ohm: 0; SizeZ_mm: 0.4mm; AEC Grade: Grade 0; Power_W: 200mW; VDC_V: 50V
R143 R144 R149 R154 = CMP-0026822-3: RES, 0, 5%, 0.063 W, AEC-Q200 Grade 0, 0402; Manufacturer: Vishay-Dale; Value: 0; Value_Code: 0000; Power_W: 63mW; Value2: 0.063W; VDC_V: 50V; TempCo: 200 ppm/C; SizeArea_mm2: 0.5; SizeX_mm: 1; SizeZ_mm: 0.6; EIA_Code: E24; AEC Category: Q200; AEC Qualified: Y
R147 = CMP-0025697-4: RES, 0, 5%, 0.1 W, AEC-Q200 Grade 0, 0603; Manufacturer: Vishay-Dale; Value: 0; Value_Code: 0000; Power_W: 100mW; Value2: 0.1W; VDC_V: 75V; TempCo: 200 ppm/C; SizeArea_mm2: 1.28; SizeX_mm: 1.6; SizeY_mm: 0.8; SizeZ_mm: 1; EIA_Code: E24; AEC Category: Q200; AEC Qualified: Y
R159 = CMP-0025951-3: RES, 100, 1%, 0.063 W, AEC-Q200 Grade 0, 0402; Manufacturer: Vishay-Dale; Value: 100; Value_Code: 100R; Power_W: 63mW; Value2: 0.063W; VDC_V: 50V; TempCo: 100 ppm/C; SizeArea_mm2: 0.5; SizeX_mm: 1; SizeZ_mm: 0.6; EIA_Code: E96; AEC Category: Q200; AEC Qualified: Y; AEC Grade: 0
R515 R516 = CMP-0022871-5: RES, 1.21 k, 1%, 0.1 W, 0603; Manufacturer: Yageo; Power_W: 100mW; TempCo: 100 ppm/C; Value_Code: 1k21; Value: 1.21k; EIA_Code: E96; SizeX_mm: 1.6; SizeY_mm: 0.8; SizeZ_mm: 1; Value2: 0.1W; SizeArea_mm2: 1.28; AEC Qualified: N; VDC_V: 75V; AEC Category: Q200; SizeAreaWB_mm2: 4.68
R551 = CMP-0026158-2: RES, 200 k, 1%, 0.063 W, AEC-Q200 Grade 0, 0402; Manufacturer: Vishay-Dale; Power_W: 63mW; TempCo: 100 ppm/C; Value: 200k; EIA_Code: E96; SizeX_mm: 1; SizeY_mm: 0.5; SizeZ_mm: 0.6; Value2: 0.063W; AEC Qualified: Y; VDC_V: 50V; AEC Category: Q200; AEC Grade: 0
T1 = CMP-0087429-1: Wideband RF transformer, SMT, RoHS; Manufacturer: Coilcraft; Ind_H: 9.5µH; DCR_ohm: 75m; Ns1toNp: 1:1; SizeZ_mm: 3.05mm; AEC Grade: Grade 3; AEC Qualified: Yes
U1 = CMP-0040579-1: 11 MHz, Precision, Low Noise, Rail-to-Rail Output, JFET Operational Amplifier, 4.5 to 36 V, -40 to 125 degC, 8-pin SOIC (D8), Green (RoHS & no Sb/Br); Manufacturer: Texas Instruments; Vio (25C)(Max)(mV): 0.12; GBW(Typ)(MHz): 11; Number of Channels: 2; Rating: Catalog; Packing: TUBE; Total Supply Voltage(Min)(+5V is 5, +/-5V is 10): 4.5; Offset Drift(Typ)(uV/C): 0.35; CMRR(Min)(dB): 126; Sub Family: High Supply Voltage Amplifier (>=30V), Low Input Bias Current Amp (<=10pA), Low Noise Amp (<=10nV/rtHz), Low Offset Voltage Amplifier (<=500uV), Precision Amplifier; Total Supply Voltage(Max)(+5V is 5, +/-5V is 10): 36; IIB(Max)(pA): 10; Slew Rate(Typ)(V/us): 20
U3 = CMP-0090241-1: Manufacturer: Texas Instruments; SizeZ_mm: 1mm; Standoff Height: 0mm
U7 = CMP-0092895-1: Variable Gain Amplifier 1 Circuit Differential 16-WQFN (4x4); Manufacturer: Texas Instruments; Standoff Height: 0mm; TJmax_C: +150°C; SizeZ_mm: 0.8mm; TaMax_C: +85°C; Response Time: 14ns; Min Supply Voltage: 3.135V; Max Supply Voltage: 5.25V; AEC Qualified: No; Number Of Channels: 1; Voltage Gain: 38.8dB; TaMin_C: -40°C; Bandwidth: 900MHz; Nominal Supply Current: 150-210mA
U22 = CMP-0860887-1: 1ns High-Speed Comparator with LVDS Outputs, RVK0012A (QFN-12); Alternate Manufacturer: Texas Instruments; SizeArea_mm2: 9; AEC Category: Q200; SizeX_mm: 3; AEC Qualified: N; SizeZ_mm: 0.8; SizeAreaWB_mm2: 16; CompType: IC

## Sheet 2_BUF802_CH2_AFE.SchDoc: 2_BUF802_CH2_AFE
size 431 x 279 mm; Date: Not shown in title block; ApprovedBy: Not shown in title block; CheckedBy: Not shown in title block; Author: Not shown in title block; CompanyName: Not shown in title block; DrawnBy: Rob Stoneham; Engineer: Not shown in title block; Organization: Not shown in title block; Address1: Not shown in title block; Address2: Not shown in title block; Address3: Not shown in title block; Address4: Not shown in title block; DocumentNumber: 3; Revision: Use project parameter SCH_Rev; SheetNumber: 3; SheetTotal: 8; PageSetup: Record=PageOptions¦CenterHorizontal=True¦CenterVertical=True¦PrintScale=1.00¦XCorrection=1.00¦YCorrection=1.00¦PrintKind=0¦BorderSize=5000000¦LeftOffset=0¦BottomOffset=0¦Orientation=2¦PaperLength=1000¦PaperWidth=1000¦Scale=100¦PaperSource=15¦PrintQuality=600¦MediaType=1¦DitherType=10¦PaperKind=Letter¦PrintScaleMode=1
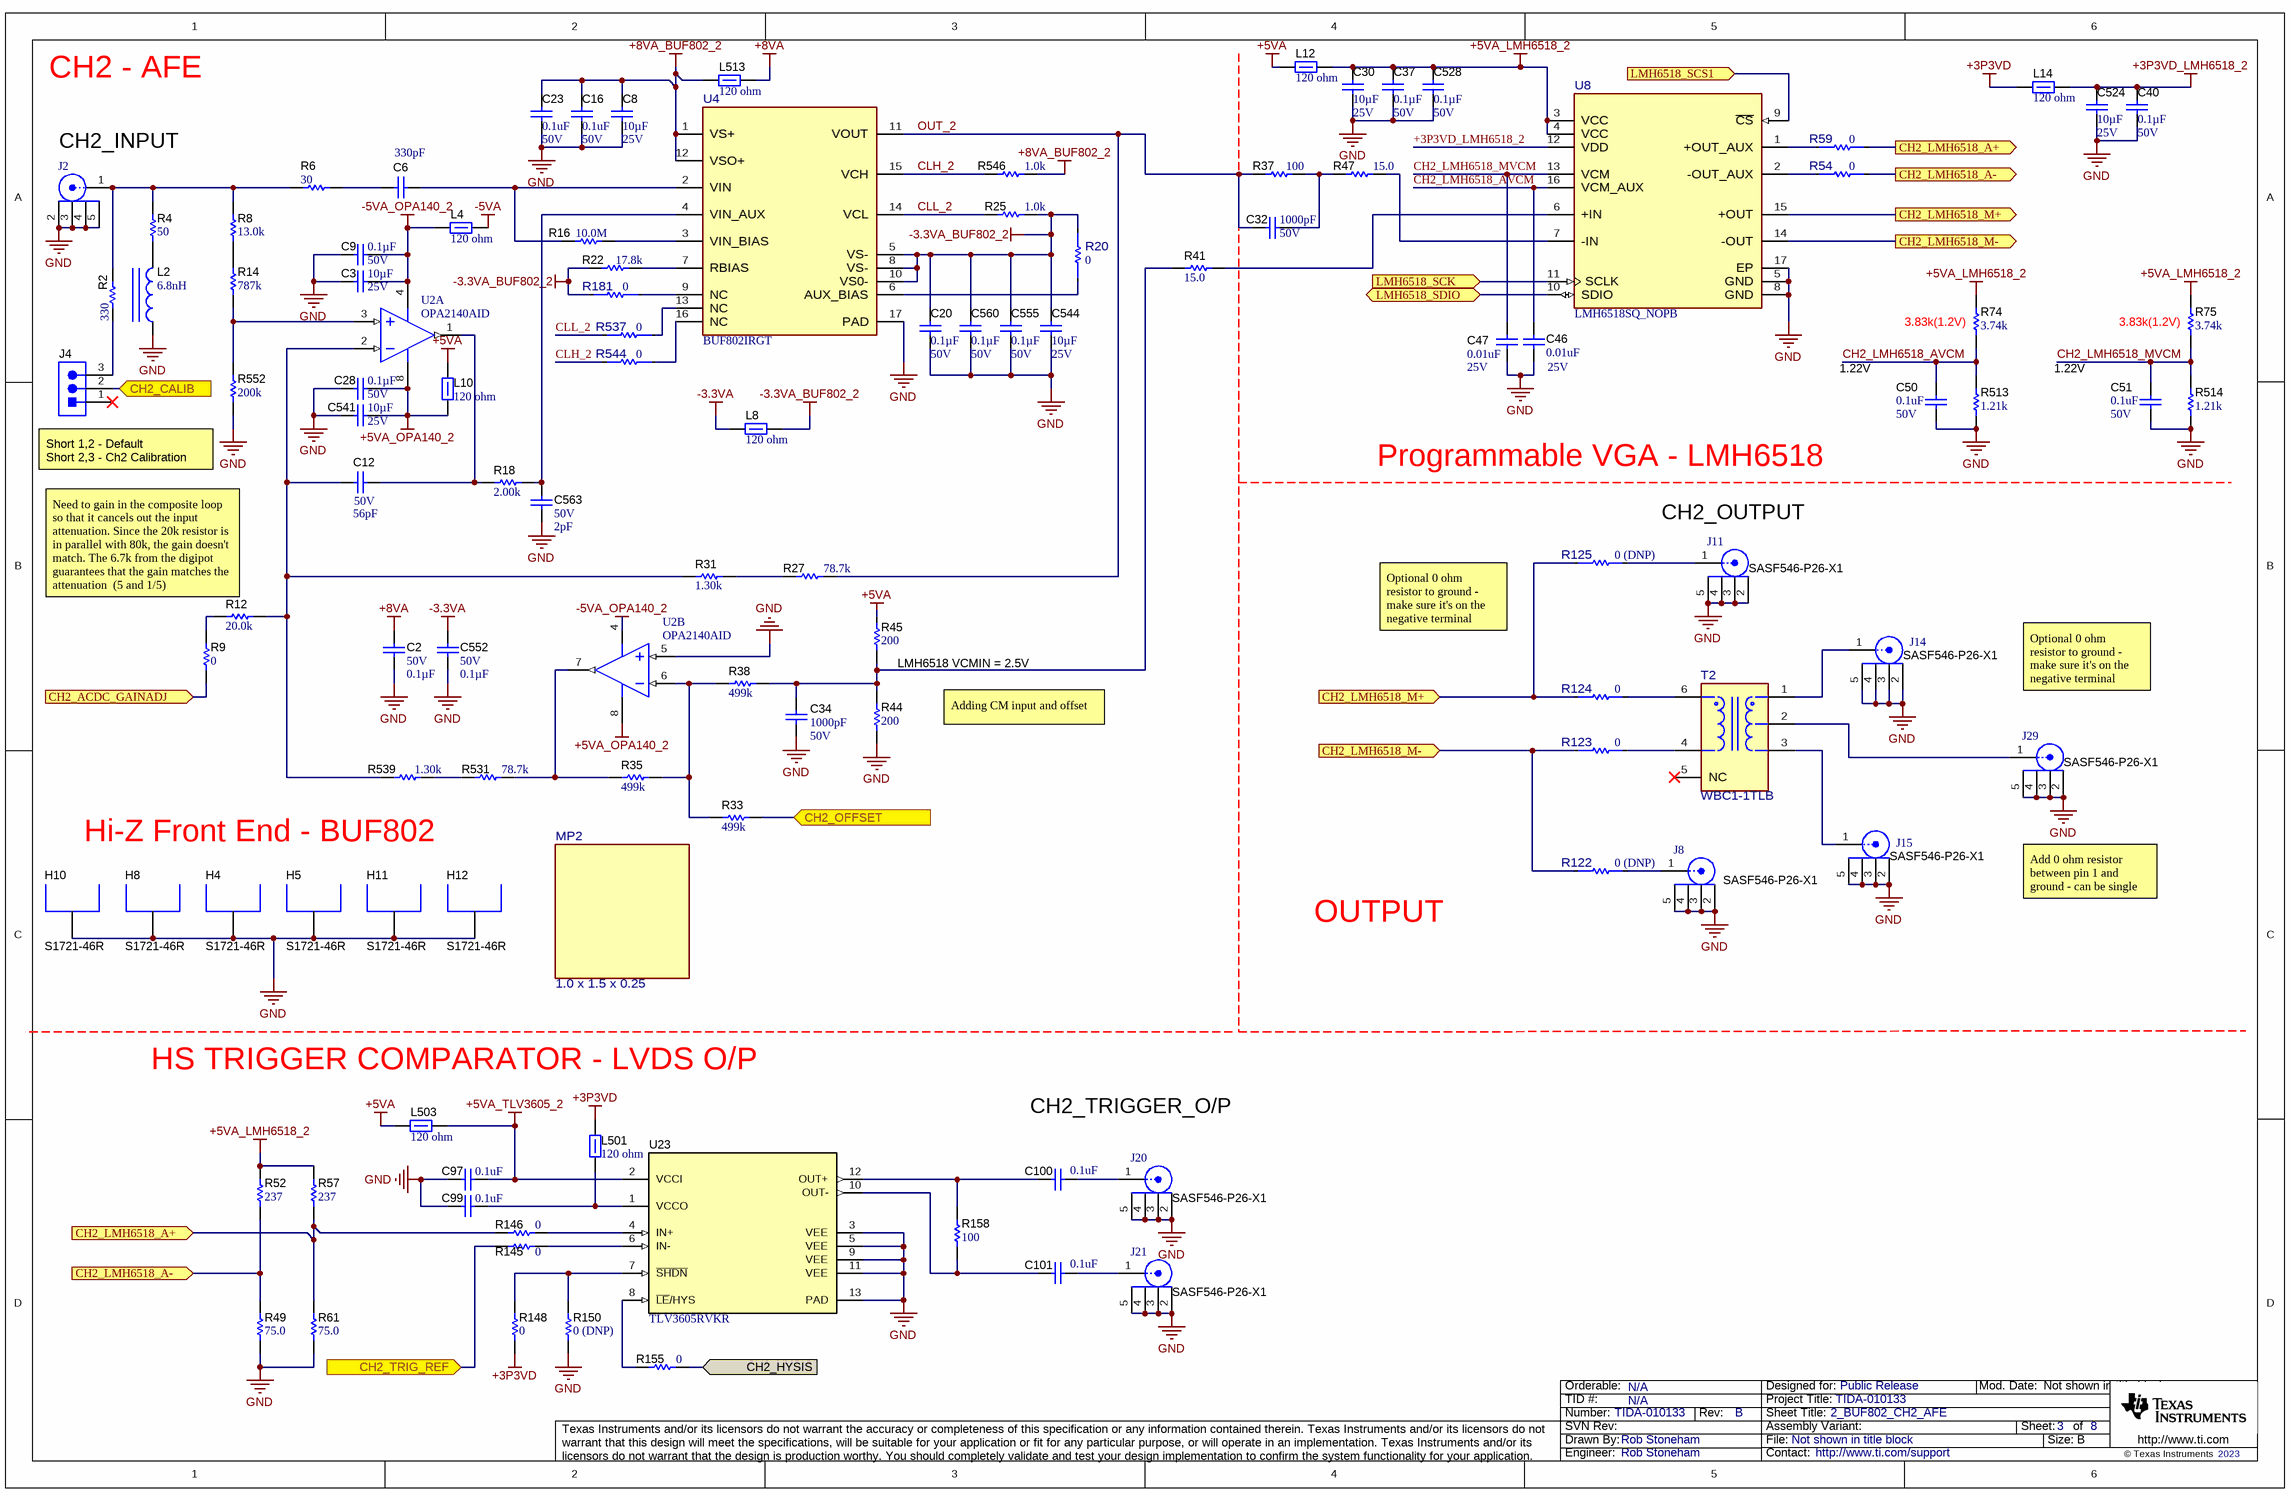
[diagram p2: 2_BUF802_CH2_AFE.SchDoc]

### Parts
C2  VDC_V: 50V  ValueDisplayed: 0.1µF  [0402]  (hidden comment: 0402BB104KW500)
C3  VDC_V: 25V  ValueDisplayed: 10µF  [0805_HV]  (hidden comment: CC0805KKX5R8BB106)
C6  ValueDisplayed: 330pF  [1206]  (hidden comment: GRM31A5C2J331JW01D)
C8  VDC_V: 25V  ValueDisplayed: 10µF  [0805_HV]  (hidden comment: CC0805KKX5R8BB106)
C9  VDC_V: 50V  ValueDisplayed: 0.1µF  [0402]  (hidden comment: 0402BB104KW500)
C12  VDC_V: 50V  ValueDisplayed: 56pF  [0402]  (hidden comment: GRM1555C1H560JA01D)
C16  ValueDisplayed: 0.1uF  Value2: 50V  [0603]  (hidden comment: CGA3E2X7R1H104K080AA)
C20  VDC_V: 50V  ValueDisplayed: 0.1µF  [0402]  (hidden comment: 0402BB104KW500)
C23  ValueDisplayed: 0.1uF  Value2: 50V  [0603]  (hidden comment: CGA3E2X7R1H104K080AA)
C28  VDC_V: 50V  ValueDisplayed: 0.1µF  [0402]  (hidden comment: 0402BB104KW500)
C30  VDC_V: 25V  ValueDisplayed: 10µF  [0805_HV]  (hidden comment: CC0805KKX5R8BB106)
C32  VDC_V: 50V  ValueDisplayed: 1000pF  [0402]  (hidden comment: 885012205061)
C34  VDC_V: 50V  ValueDisplayed: 1000pF  [0402]  (hidden comment: 885012205061)
C37  VDC_V: 50V  ValueDisplayed: 0.1µF  [0402]  (hidden comment: 0402BB104KW500)
C40  VDC_V: 50V  ValueDisplayed: 0.1µF  [0402]  (hidden comment: 0402BB104KW500)
C46  ValueDisplayed: 0.01uF  VDC_V: 25V  [0306]  (hidden comment: LLL185R71E103MA01L)
C47  ValueDisplayed: 0.01uF  VDC_V: 25V  [0306]  (hidden comment: LLL185R71E103MA01L)
C50  ValueDisplayed: 0.1uF  VDC_V: 50V  [0603]  (hidden comment: CGA3E2X7R1H104K080AA)
C51  ValueDisplayed: 0.1uF  VDC_V: 50V  [0603]  (hidden comment: CGA3E2X7R1H104K080AA)
C97  ValueDisplayed: 0.1uF  [0603]  (hidden comment: CGA3E2X7R1H104K080AA)
C99  ValueDisplayed: 0.1uF  [0603]  (hidden comment: CGA3E2X7R1H104K080AA)
C100  ValueDisplayed: 0.1uF  [0402]  (hidden comment: C1005X7R1E104M050BB)
C101  ValueDisplayed: 0.1uF  [0402]  (hidden comment: C1005X7R1E104M050BB)
C524  VDC_V: 25V  ValueDisplayed: 10µF  [0805_HV]  (hidden comment: CC0805KKX5R8BB106)
C528  VDC_V: 50V  ValueDisplayed: 0.1µF  [0402]  (hidden comment: 0402BB104KW500)
C541  VDC_V: 25V  ValueDisplayed: 10µF  [0805_HV]  (hidden comment: CC0805KKX5R8BB106)
C544  VDC_V: 25V  ValueDisplayed: 10µF  [0805_HV]  (hidden comment: CC0805KKX5R8BB106)
C552  VDC_V: 50V  ValueDisplayed: 0.1µF  [0402]  (hidden comment: 0402BB104KW500)
C555  VDC_V: 50V  ValueDisplayed: 0.1µF  [0402]  (hidden comment: 0402BB104KW500)
C560  VDC_V: 50V  ValueDisplayed: 0.1µF  [0402]  (hidden comment: 0402BB104KW500)
C563  VDC_V: 50V  ValueDisplayed: 2pF  [0603]  (hidden comment: C0603C209C5GACTU)
H4  S1721-46R  [Harwin_S1721-46R]
H5  S1721-46R  [Harwin_S1721-46R]
H8  S1721-46R  [Harwin_S1721-46R]
H10  S1721-46R  [Harwin_S1721-46R]
H11  S1721-46R  [Harwin_S1721-46R]
H12  S1721-46R  [Harwin_S1721-46R]
J2  142-0701-851  [Emerson_142-0701-851]  (value not drawn)
J4  22284030  [Molex_0022284030]  (value not drawn)
J8  SASF546-P26-X1  [CONN_LTI_SASF546-P26-X1]
J11  SASF546-P26-X1  [CONN_LTI_SASF546-P26-X1]
J14  SASF546-P26-X1  [CONN_LTI_SASF546-P26-X1]
J15  SASF546-P26-X1  [CONN_LTI_SASF546-P26-X1]
J20  SASF546-P26-X1  [CONN_LTI_SASF546-P26-X1]
J21  SASF546-P26-X1  [CONN_LTI_SASF546-P26-X1]
J29  SASF546-P26-X1  [CONN_LTI_SASF546-P26-X1]
L2  ValueDisplayed: 6.8nH  [LQG15WZ_02]  (hidden comment: LQG15WZ6N8J02D)
L4  ValueDisplayed: 120 ohm  [0603]  (hidden comment: BLM18SG121TN1D)
L8  ValueDisplayed: 120 ohm  [0603]  (hidden comment: BLM18SG121TN1D)
L10  ValueDisplayed: 120 ohm  [0603]  (hidden comment: BLM18SG121TN1D)
L12  ValueDisplayed: 120 ohm  [0603]  (hidden comment: BLM18SG121TN1D)
L14  ValueDisplayed: 120 ohm  [0603]  (hidden comment: BLM18SG121TN1D)
L501  ValueDisplayed: 120 ohm  [0603]  (hidden comment: BLM18SG121TN1D)
L503  ValueDisplayed: 120 ohm  [0603]  (hidden comment: BLM18SG121TN1D)
L513  ValueDisplayed: 120 ohm  [0603]  (hidden comment: BLM18SG121TN1D)
MP2  1.0 x 1.5 x 0.25  [FP-1.0 x 1.5 x 0.25_RF_SHIELD-MFG]
R2  ValueDisplayed: 330  [0603]  (hidden comment: RC0603FR-07330RL)
R4  ValueDisplayed: 50  [0603]  (hidden comment: FC0603E50R0BTBST1)
R6  ValueDisplayed: 30  [0402]  (hidden comment: CRCW040230R0JNED)
R8  ValueDisplayed: 13.0k  [0402L]  (hidden comment: CRCW040213K0FKED)
R9  ValueDisplayed: 0  [0603]  (hidden comment: CRCW06030000Z0EA)
R12  ValueDisplayed: 20.0k  [0402]  (hidden comment: CRCW040220K0FKED)
R14  ValueDisplayed: 787k  [0402L]  (hidden comment: CRCW0402787KFKED)
R16  ValueDisplayed: 10.0M  [0402]  (hidden comment: CRCW040210M0FKED)
R18  ValueDisplayed: 2.00k  [0402]  (hidden comment: ERJ-2RKF2001X)
R20  value 0  [FP-ERJ-2GE0R00X_0402-MFG]  (hidden comment: ERJ-2GE0R00X)
R22  ValueDisplayed: 17.8k  [0402]  (hidden comment: CRCW040217K8FKED)
R25  ValueDisplayed: 1.0k  [0603]  (hidden comment: RC0603JR-071KL)
R27  ValueDisplayed: 78.7k  [0402]  (hidden comment: CRCW040278K7FKED)
R31  ValueDisplayed: 1.30k  [0402]  (hidden comment: CRCW04021K30FKED)
R33  ValueDisplayed: 499k  [0402]  (hidden comment: CRCW0402499KFKED)
R35  ValueDisplayed: 499k  [0402]  (hidden comment: CRCW0402499KFKED)
R37  ValueDisplayed: 100  [0402]  (hidden comment: CRCW0402100RFKED)
R38  ValueDisplayed: 499k  [0402]  (hidden comment: CRCW0402499KFKED)
R41  ValueDisplayed: 15.0  [0402]  (hidden comment: CRCW040215R0FKED)
R44  ValueDisplayed: 200  [0402]  (hidden comment: CRCW0402200RFKED)
R45  ValueDisplayed: 200  [0402]  (hidden comment: CRCW0402200RFKED)
R47  ValueDisplayed: 15.0  [0402]  (hidden comment: CRCW040215R0FKED)
R49  ValueDisplayed: 75.0  [0603]  (hidden comment: CRCW060375R0FKEA)
R52  ValueDisplayed: 237  [0603]  (hidden comment: CRCW0603237RFKEA)
R54  value 0  [FP-CRCW04020000Z0EDHP_0402-MFG]  (hidden comment: CRCW04020000Z0EDHP)
R57  ValueDisplayed: 237  [0603]  (hidden comment: CRCW0603237RFKEA)
R59  value 0  [FP-CRCW04020000Z0EDHP_0402-MFG]  (hidden comment: CRCW04020000Z0EDHP)
R61  ValueDisplayed: 75.0  [0603]  (hidden comment: CRCW060375R0FKEA)
R74  ValueDisplayed: 3.74k  [0603]  (hidden comment: RC0603FR-073K74L)
R75  ValueDisplayed: 3.74k  [0603]  (hidden comment: RC0603FR-073K74L)
R122  value 0 (DNP)  [FP-CRCW04020000Z0EDHP_0402-MFG]  (hidden comment: CRCW04020000Z0EDHP)
R123  value 0  [FP-CRCW04020000Z0EDHP_0402-MFG]  (hidden comment: CRCW04020000Z0EDHP)
R124  value 0  [FP-CRCW04020000Z0EDHP_0402-MFG]  (hidden comment: CRCW04020000Z0EDHP)
R125  value 0 (DNP)  [FP-CRCW04020000Z0EDHP_0402-MFG]  (hidden comment: CRCW04020000Z0EDHP)
R145  ValueDisplayed: 0  [0402]  (hidden comment: CRCW04020000Z0ED)
R146  ValueDisplayed: 0  [0402]  (hidden comment: CRCW04020000Z0ED)
R148  ValueDisplayed: 0  [0603]  (hidden comment: CRCW06030000Z0EA)
R150  ValueDisplayed: 0 (DNP)  [0402]  (hidden comment: CRCW04020000Z0ED)
R155  ValueDisplayed: 0  [0402]  (hidden comment: CRCW04020000Z0ED)
R158  ValueDisplayed: 100  [0402]  (hidden comment: CRCW0402100RFKED)
R181  value 0  [FP-ERJ-2GE0R00X_0402-MFG]  (hidden comment: ERJ-2GE0R00X)
R513  ValueDisplayed: 1.21k  [0603]  (hidden comment: RC0603FR-071K21L)
R514  ValueDisplayed: 1.21k  [0603]  (hidden comment: RC0603FR-071K21L)
R531  ValueDisplayed: 78.7k  [0402]  (hidden comment: CRCW040278K7FKED)
R537  value 0  [FP-ERJ-2GE0R00X_0402-MFG]  (hidden comment: ERJ-2GE0R00X)
R539  ValueDisplayed: 1.30k  [0402]  (hidden comment: CRCW04021K30FKED)
R544  value 0  [FP-ERJ-2GE0R00X_0402-MFG]  (hidden comment: ERJ-2GE0R00X)
R546  ValueDisplayed: 1.0k  [0603]  (hidden comment: RC0603JR-071KL)
R552  ValueDisplayed: 200k  [0402L]  (hidden comment: CRCW0402200KFKED)
T2  WBC1-1TLB  [FP-WBC1-1TLB_SMT_XFRMR_3MM81_3MM81-MFG]
U2  OPA2140AID  [D0008A_N]  (parts A,B of 2)
U4  BUF802IRGT  [RGT0016C-MFG]
U8  LMH6518SQ_NOPB  [RGH0016A-MFG]
U23  TLV3605RVKR  [RVK0012A]

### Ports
CH2_ACDC_GAINADJ (in), CH2_CALIB (in), CH2_HYSIS (in), CH2_LMH6518_A+ (in), CH2_LMH6518_A+ (out), CH2_LMH6518_A- (in), CH2_LMH6518_A- (out), CH2_LMH6518_M+ (in), CH2_LMH6518_M+ (out), CH2_LMH6518_M- (in), CH2_LMH6518_M- (out), CH2_OFFSET (in), CH2_TRIG_REF (in), LMH6518_SCK (in), LMH6518_SCS1 (in), LMH6518_SDIO (bidir)

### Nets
+3P3VD: L14.1 L501.2 R148.1
+3P3VD_LMH6518_2: C40.1 C524.1 L14.2 U8.12(VDD)
+5VA: L10.2 L12.2 L503.1 R45.2
+5VA_LMH6518_2: C30.1 C37.1 C528.1 L12.1 R52.2 R57.2 R74.2 R75.2 U8.3(VCC) U8.4(VCC)
+5VA_OPA140_2: C28.2 C541.2 L10.1 U2.8(V+)
+5VA_TLV3605_2: C97.2 L503.2 U23.2(VCCI)
+8VA: C2.1 L513.2
+8VA_BUF802_2: C8.1 C16.1 C23.1 L513.1 R546.2 U4.1(VS+) U4.12(VSO+)
-3.3VA: C552.2 L8.1
-3.3VA_BUF802_2: C20.1 C544.1 C555.1 C560.1 L8.2 R20.2 R22.1 R25.2 R181.2 U4.5(VS-) U4.8(VS-) U4.10(VS0-)
-5VA: L4.2
-5VA_OPA140_2: C3.2 C9.2 L4.1 U2.4(V-)
GND: C2.2 C3.1 C8.2 C9.1 C16.2 C20.2 C23.2 C28.1 C30.2 C34.2 C37.2 C40.2 C46.2 C47.2 C50.2 C51.2 C97.1 C99.2 C524.2 C528.2 C541.1 C544.2 C552.1 C555.2 C560.2 C563.2 H4.1 H5.1 H8.1 H10.1 H11.1 H12.1 J2.2 J2.3 J2.4 J2.5 J8.2 J8.3 J8.4 J8.5 J11.2 J11.3 J11.4 J11.5 J14.2 J14.3 J14.4 J14.5 J15.2 J15.3 J15.4 J15.5 J20.2 J20.3 J20.4 J20.5 J21.2 J21.3 J21.4 J21.5 J29.2 J29.3 J29.4 J29.5 L2.1 R44.1 R49.1 R61.1 R150.1 R513.1 R514.1 R552.1 U2.5(IN_B+) U4.17(PAD) U8.5(GND) U8.8(GND) U8.17(EP) U23.3(VEE) U23.5(VEE) U23.9(VEE) U23.11(VEE) U23.13(PAD)
CH2_ACDC_GAINADJ: R9.2 ; port CH2_ACDC_GAINADJ
CH2_CALIB: J4.2 ; port CH2_CALIB
CH2_HYSIS: R155.2 ; port CH2_HYSIS
CH2_LMH6518_A+: R57.1 R59.2 R61.2 R146.1 ; port CH2_LMH6518_A+
CH2_LMH6518_A-: R49.2 R52.1 R54.2 ; port CH2_LMH6518_A-
CH2_LMH6518_AVCM: C46.1 C50.1 R74.1 R513.2 U8.16(VCM_AUX)
CH2_LMH6518_M+: R124.1 R125.1 U8.15(+OUT) ; port CH2_LMH6518_M+
CH2_LMH6518_M-: R122.1 R123.1 U8.14(-OUT) ; port CH2_LMH6518_M-
CH2_LMH6518_MVCM: C47.1 C51.1 R75.1 R514.2 U8.13(VCM)
CH2_OFFSET: R33.2 ; port CH2_OFFSET
CH2_TRIG_REF: R145.1 ; port CH2_TRIG_REF
CLH_2: R544.2 R546.1 U4.15(VCH)
CLL_2: R25.1 R537.2 U4.14(VCL)
LMH6518_SCK: U8.11(SCLK) ; port LMH6518_SCK
LMH6518_SCS1: U8.9(~{CS}) ; port LMH6518_SCS1
LMH6518_SDIO: U8.10(SDIO) ; port LMH6518_SDIO
OUT_2: C32.1 R27.2 R37.1 U4.11(VOUT)
NetC6_1: C6.1 R16.1 U4.2(VIN)
NetC6_2: C6.2 R6.2
NetC12_1: C12.1 R18.1 U2.1(OUT_A)
NetC12_2: C12.2 R12.2 R31.1 R539.1 U2.2(IN_A-)
NetC32_2: C32.2 R37.2 R47.1
NetC34_1: C34.1 R38.2 R41.1 R44.2 R45.1
NetC99_1: C99.1 L501.1 U23.1(VCCO)
NetC100_1: C100.1 R158.2 U23.12(OUT+)
NetC100_2: C100.2 J20.1
NetC101_1: C101.1 R158.1 U23.10(OUT-)
NetC101_2: C101.2 J21.1
NetC563_1: C563.1 R18.2 U4.4(VIN_AUX)
NetJ2_1: J2.1 R2.2 R4.2 R6.1 R8.2
NetJ4_3: J4.3 R2.1
NetJ8_1: J8.1 R122.2
NetJ11_1: J11.1 R125.2
NetJ14_1: J14.1 T2.1
NetJ15_1: J15.1 T2.3
NetJ29_1: J29.1 T2.2
NetL2_2: L2.2 R4.1
NetR8_1: R8.1 R14.2
NetR9_1: R9.1 R12.1
NetR14_1: R14.1 R552.2 U2.3(IN_A+)
NetR16_2: R16.2 U4.3(VIN_BIAS)
NetR20_1: R20.1 U4.6(AUX_BIAS)
NetR22_2: R22.2 U4.7(RBIAS)
NetR27_1: R27.1 R31.2
NetR33_1: R33.1 R35.2 R38.1 U2.6(IN_B-)
NetR35_1: R35.1 R531.2 U2.7(OUT_B)
NetR41_2: R41.2 U8.6(+IN)
NetR47_2: R47.2 U8.7(-IN)
NetR54_1: R54.1 U8.2(-OUT_AUX)
NetR59_1: R59.1 U8.1(+OUT_AUX)
NetR123_2: R123.2 T2.4
NetR124_2: R124.2 T2.6
NetR145_2: R145.2 U23.6(IN-)
NetR146_2: R146.2 U23.4(IN+)
NetR148_2: R148.2 R150.2 U23.7(~{SHDN})
NetR155_1: R155.1 U23.8(~{LE}/HYS)
NetR181_1: R181.1 U4.9(NC)
NetR531_1: R531.1 R539.2
NetR537_1: R537.1 U4.13(NC)
NetR544_1: R544.1 U4.16(NC)

Not connected (* = marked no-connect by the designer): J4 1*; T2 5(NC)*

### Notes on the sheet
- CH2 - AFE
- (near J2) CH2_INPUT
- 1.22V
- (near R74) 3.83k(1.2V)
- (near R75) 3.83k(1.2V)
- Short 1,2 - Default
  Short 2,3 - Ch2 Calibration
- Programmable VGA - LMH6518
- (near J11) CH2_OUTPUT
- (near R12) Need to gain in the composite loop so that it cancels out the input attenuation. Since the 20k resistor is in parallel with 80k, the gain doesn't match. The 6.7k from the digipot guarantees that the gain matches the attenuation  (5 and 1/5)
- Optional 0 ohm resistor to ground - make sure it's on the negative terminal
- LMH6518 VCMIN = 2.5V
- Adding CM input and offset
- Hi-Z Front End - BUF802
- OUTPUT
- Add 0 ohm resistor between pin 1 and ground - can be single ended or differential
- HS TRIGGER COMPARATOR - LVDS O/P
- CH2_TRIGGER_O/P

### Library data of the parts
C2 C9 C20 C28 C37 C40 C528 C552 C555 C560 = CMP-0860983-1: as C1 on sheet 1_BUF802_CH1_AFE
C3 C8 C30 C524 C541 C544 = CMP-0084177-1: as C4 on sheet 1_BUF802_CH1_AFE
C6 = CMP-0008887-2: as C5 on sheet 1_BUF802_CH1_AFE
C12 = CMP-0006478-2: as C11 on sheet 1_BUF802_CH1_AFE
C16 C23 C50 C51 = CMP-0007078-4: as C15 on sheet 1_BUF802_CH1_AFE
C32 C34 = CMP-0006231-2: as C31 on sheet 1_BUF802_CH1_AFE
C46 C47 = CMP-0009490-2: as C44 on sheet 1_BUF802_CH1_AFE
C97 C99 = CMP-0007078-4: as C96 on sheet 1_BUF802_CH1_AFE
C100 C101 = CMP-0006295-2: as C102 on sheet 1_BUF802_CH1_AFE
C563 = CMP-0006891-4: as C562 on sheet 1_BUF802_CH1_AFE
H4 H5 H8 H10-H12 = CMP-0086134-1: as H3 on sheet 1_BUF802_CH1_AFE
J2 = CMP-0055822-3: as J1 on sheet 1_BUF802_CH1_AFE
J4 = CMP-0078237-1: as J3 on sheet 1_BUF802_CH1_AFE
J8 J11 J14 J15 J20 J21 J29 = CMP-0055826-1: as J9 on sheet 1_BUF802_CH1_AFE
L2 = CMP-0080319-3: as L1 on sheet 1_BUF802_CH1_AFE
L4 L8 L10 L12 L14 L501 L503 L513 = CMP-0003352-2: as L3 on sheet 1_BUF802_CH1_AFE
MP2 = CMP-0096146-1: as MP1 on sheet 1_BUF802_CH1_AFE
R2 = CMP-0023033-5: as R1 on sheet 1_BUF802_CH1_AFE
R4 = CMP-0023387-3: as R3 on sheet 1_BUF802_CH1_AFE
R6 = CMP-0026904-3: as R5 on sheet 1_BUF802_CH1_AFE
R8 = CMP-0026003-3: as R7 on sheet 1_BUF802_CH1_AFE
R9 = CMP-0025697-4: as R10 on sheet 1_BUF802_CH1_AFE
R12 = CMP-0026162-2: as R11 on sheet 1_BUF802_CH1_AFE
R14 = CMP-0026549-2: as R13 on sheet 1_BUF802_CH1_AFE
R16 = CMP-0025962-3: as R15 on sheet 1_BUF802_CH1_AFE
R18 = CMP-0026676-1: as R17 on sheet 1_BUF802_CH1_AFE
R20 R181 R537 R544 = CMP-0002710-1: as R19 on sheet 1_BUF802_CH1_AFE
R22 = CMP-0026051-3: as R21 on sheet 1_BUF802_CH1_AFE
R25 R546 = CMP-0025899-5: as R24 on sheet 1_BUF802_CH1_AFE
R27 R531 = CMP-0026551-2: as R26 on sheet 1_BUF802_CH1_AFE
R31 R539 = CMP-0026082-3: as R30 on sheet 1_BUF802_CH1_AFE
R33 R35 R38 = CMP-0026401-2: as R32 on sheet 1_BUF802_CH1_AFE
R37 = CMP-0025951-3: as R36 on sheet 1_BUF802_CH1_AFE
R41 R47 = CMP-0026030-3: as R40 on sheet 1_BUF802_CH1_AFE
R44 R45 = CMP-0026159-2: as R42 on sheet 1_BUF802_CH1_AFE
R49 R61 = CMP-0022590-4: as R48 on sheet 1_BUF802_CH1_AFE
R52 R57 = CMP-0022227-5: as R51 on sheet 1_BUF802_CH1_AFE
R54 R59 R123 R124 = CMP-0001606-2: as R53 on sheet 1_BUF802_CH1_AFE
R74 R75 = CMP-0023087-5: as R72 on sheet 1_BUF802_CH1_AFE
R122 R125 = CMP-0001606-2: as R118 on sheet 1_BUF802_CH1_AFE
R145 R146 R150 R155 = CMP-0026822-3: as R143 on sheet 1_BUF802_CH1_AFE
R148 = CMP-0025697-4: as R147 on sheet 1_BUF802_CH1_AFE
R158 = CMP-0025951-3: as R159 on sheet 1_BUF802_CH1_AFE
R513 R514 = CMP-0022871-5: as R515 on sheet 1_BUF802_CH1_AFE
R552 = CMP-0026158-2: as R551 on sheet 1_BUF802_CH1_AFE
T2 = CMP-0087429-1: as T1 on sheet 1_BUF802_CH1_AFE
U2 = CMP-0040579-1: as U1 on sheet 1_BUF802_CH1_AFE
U4 = CMP-0090241-1: as U3 on sheet 1_BUF802_CH1_AFE
U8 = CMP-0092895-1: as U7 on sheet 1_BUF802_CH1_AFE
U23 = CMP-0860887-1: as U22 on sheet 1_BUF802_CH1_AFE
